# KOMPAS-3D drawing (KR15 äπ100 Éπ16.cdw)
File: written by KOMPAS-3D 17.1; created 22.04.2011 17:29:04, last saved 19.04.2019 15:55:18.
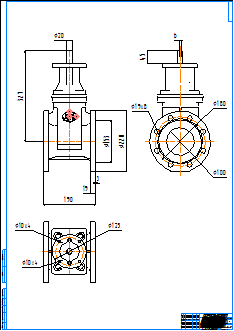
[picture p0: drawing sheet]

Title block, sheet 1: name: KR15 Ду100 Ру16; material: Внимание! Данный продукт является объектом авторского права ООО «Торговый Дом АДЛ». / Запрещается изменение, копирование, распространение / (в том числе путем копирования на другие сайты и ресурсы в Интернете) / или любое иное использование информации и объектов без предварительного / согласия правообладателя (ООО «Торговый Дом АДЛ»).; scale: 1:1; sheets: 1; organisation: ООО "Торговый дом АДЛ"; sheet format: A0; stored path: \\adlc.lan\data\АДЛ_ПКД\3D-модели\ADL production\Клиновые задвижки серии KR ГРАНАР\Клиновые задвижки KR15\С голым штоком\KOMPAS 2D\KR15 Ду100 Ру16.cdw

Views: Спереди 4, Проекционный вид 5, Проекционный вид 6
Dimensions and other numbers on the sheet: 153; 220; 190; 19; 3; 327; 20; 125; 10; 6; 100; 180; 45; 1:1; 1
